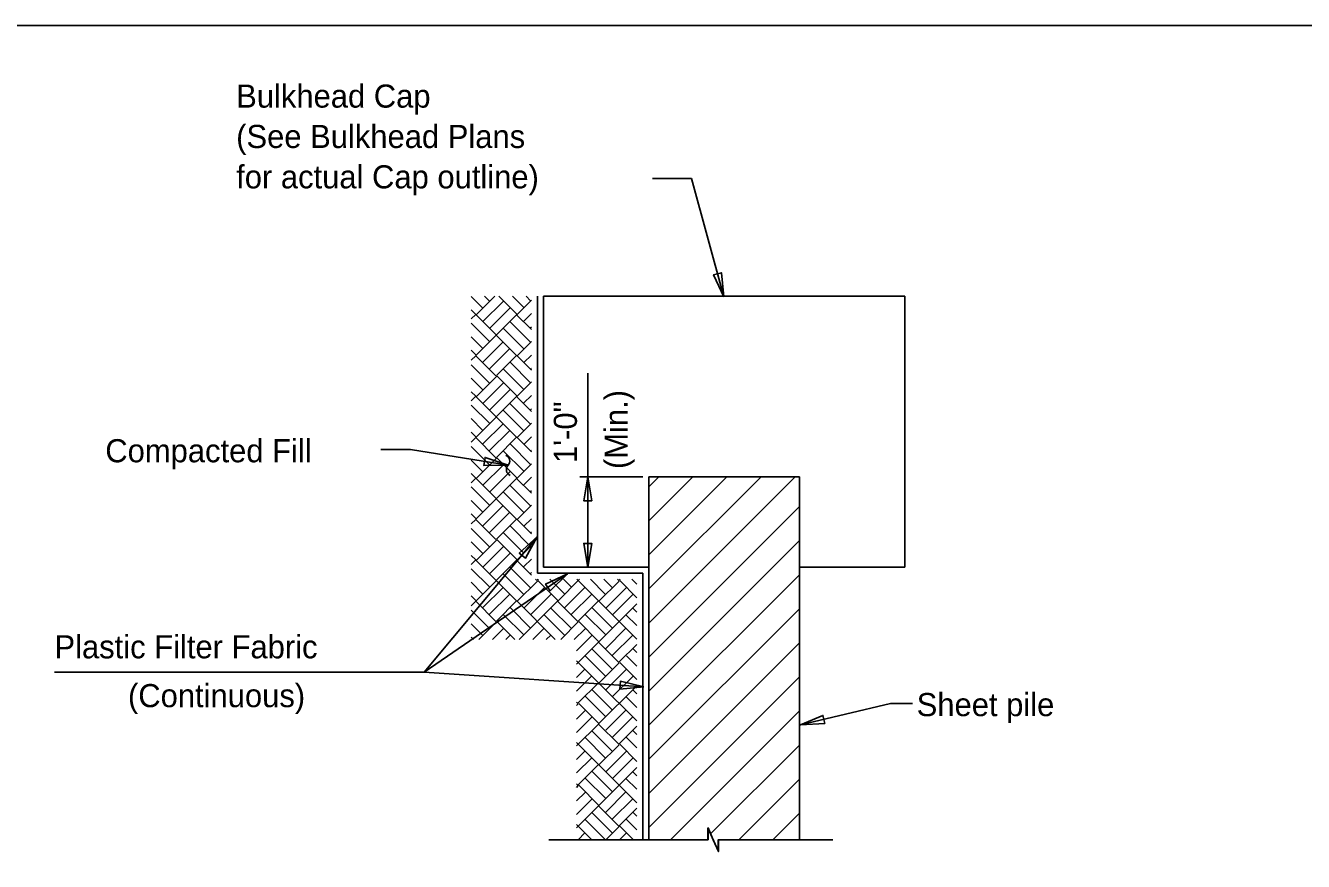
# Model space of a CAD drawing. Extents: x 111162.5 to 111216.6, y 110741.1 to 110776.1.
# Drawn here: x 111170.9 to 111179.25, y 110768.77 to 110774.24 of the extents above; entities that cross this region are included whole.
import ezdxf

# ---------------------------------------------------------------- set-up
doc = ezdxf.new("R2010")
doc.units = 0
for name, color, linetype in [('AdhocPoint_dp', 7, 'Continuous'), ('Border', 7, 'Continuous'), ('Patterning', 7, 'Continuous'), ('PlotBorder_dp', 7, 'Continuous'), ('SheetBorder_dp', 7, 'Continuous'), ('TextMisc', 7, 'Continuous'), ('Viewport', 7, 'Continuous')]:
    doc.layers.add(name, color=color, linetype=linetype)

msp = doc.modelspace()

# ---------------------------------------------------------------- linework, layer by layer
at = {"layer": 'AdhocPoint_dp'}
for p, q in [((111174.2855, 110770.6961), (111174.2855, 110772.468)), ((111174.2855, 110772.468), (111176.6479, 110772.468)), ((111176.6479, 110772.468), (111176.6479, 110770.6961)), ((111174.9745, 110770.6961), (111174.2855, 110770.6961)), ((111175.9589, 110770.6961), (111176.6479, 110770.6961))]:
    msp.add_line(p, q, dxfattribs=at)
at = {"layer": 'Border'}
for p, q in [((111174.2461, 110770.6567), (111174.2461, 110772.468)), ((111174.9351, 110770.6567), (111174.2461, 110770.6567)), ((111174.9351, 110768.914), (111174.9351, 110770.6567))]:
    msp.add_line(p, q, dxfattribs=at)
at = {"layer": 'Patterning'}
for p, q in [((111174.5752, 110770.6961), (111174.5752, 110771.9642)), ((111174.934, 110771.2867), (111174.5228, 110771.2867)), ((111174.443, 110770.6523), (111173.5051, 110770.0105)), ((111174.9422, 110769.9147), (111173.5051, 110770.0105)), ((111174.3208, 110768.914), (111175.2889, 110768.914)), ((111175.4996, 110768.914), (111176.1761, 110768.914))]:
    msp.add_line(p, q, dxfattribs=at)
for points in [[(111175.4639, 110772.4646), (111175.2528, 110773.2371), (111174.9989, 110773.2371)], [(111174.0543, 110771.3626), (111173.417, 110771.4664), (111173.2225, 110771.4664)], [(111174.2451, 110770.8947), (111173.5051, 110770.0105), (111171.0902, 110770.0105)], [(111175.9661, 110769.6648), (111176.5542, 110769.8045), (111176.698, 110769.8045)], [(111175.2889, 110768.914), (111175.3608, 110768.914), (111175.3608, 110768.9921), (111175.4277, 110768.8409), (111175.4277, 110768.914), (111175.4996, 110768.914)], [(111175.2892, 110768.914), (111175.3617, 110768.914), (111175.3617, 110768.9915), (111175.3954, 110768.914), (111175.4292, 110768.8365), (111175.4292, 110768.914), (111175.5017, 110768.914)]]:
    msp.add_lwpolyline(points, dxfattribs=at)
for points in [[(111175.4639, 110772.4646), (111175.4487, 110772.6223), (111175.3976, 110772.6085)], [(111174.0543, 110771.3626), (111173.9044, 110771.4138), (111173.8959, 110771.3616)], [(111174.5752, 110771.2867), (111174.5487, 110771.1305), (111174.6016, 110771.1305)], [(111174.2451, 110770.8947), (111174.1271, 110770.789), (111174.1685, 110770.756)], [(111174.5752, 110770.6961), (111174.6016, 110770.8523), (111174.5487, 110770.8523)], [(111174.443, 110770.6523), (111174.2993, 110770.5856), (111174.3293, 110770.542)], [(111174.9422, 110769.9147), (111174.788, 110769.9511), (111174.7846, 110769.8983)], [(111175.9661, 110769.6648), (111176.1242, 110769.6753), (111176.1119, 110769.7268)]]:
    msp.add_lwpolyline(points, close=True, dxfattribs=at)
for centre, start, end in [((111174.025, 110771.3908), 316.04656, 67.77378), ((111174.0836, 110771.3344), 136.04656, 247.77378)]:
    msp.add_arc(centre, 0.0406, start, end, dxfattribs=at)
at = {"layer": 'PlotBorder_dp'}
for p, q in [((111174.9745, 110768.914), (111174.9745, 110771.2867)), ((111174.9745, 110771.2867), (111175.9589, 110771.2867)), ((111175.9589, 110771.2867), (111175.9589, 110768.914))]:
    msp.add_line(p, q, dxfattribs=at)
at = {"layer": 'TextMisc'}
for p, q in [((111173.813, 110772.4675), (111173.887, 110772.3934)), ((111173.9671, 110772.468), (111173.8455, 110772.3464)), ((111174.0224, 110772.4348), (111173.8898, 110772.3021)), ((111173.9007, 110772.468), (111173.9311, 110772.4376)), ((111174.1132, 110772.3496), (111173.9948, 110772.468)), ((111174.1573, 110772.3937), (111174.0831, 110772.468)), ((111174.2067, 110772.443), (111174.1132, 110772.3496)), ((111174.2016, 110772.438), (111174.1717, 110772.468)), ((111173.8428, 110772.3492), (111173.813, 110772.379)), ((111173.8428, 110772.3492), (111173.813, 110772.3194)), ((111174.1103, 110772.0816), (111173.8455, 110772.3464)), ((111174.1105, 110772.3468), (111173.8456, 110772.082)), ((111174.0666, 110772.3906), (111173.9339, 110772.258)), ((111174.1105, 110772.3468), (111174.2067, 110772.2505)), ((111174.2067, 110772.3548), (111174.1573, 110772.3055)), ((111173.9341, 110772.1704), (111173.813, 110772.2915)), ((111174.0661, 110772.3025), (111174.1987, 110772.17)), ((111174.2067, 110772.2665), (111174.2015, 110772.2613)), ((111173.8898, 110772.1261), (111173.813, 110772.203)), ((111174.022, 110772.2584), (111174.1546, 110772.1259)), ((111173.8456, 110772.082), (111173.813, 110772.1147)), ((111174.0219, 110772.17), (111173.8898, 110772.0379)), ((111174.066, 110772.1259), (111173.9339, 110771.9938)), ((111174.2067, 110772.1724), (111174.1131, 110772.0788)), ((111173.8429, 110772.0792), (111173.813, 110772.0493)), ((111173.813, 110772.0206), (111173.9311, 110771.9024)), ((111173.8429, 110772.0792), (111173.9754, 110771.9467)), ((111174.1103, 110772.0816), (111173.9782, 110771.9495)), ((111174.2016, 110771.9029), (111174.0694, 110772.0351)), ((111174.2067, 110771.9852), (111174.1131, 110772.0788)), ((111174.2067, 110772.0839), (111174.1573, 110772.0345)), ((111173.813, 110771.9323), (111173.887, 110771.8583)), ((111173.9782, 110771.9439), (111173.8455, 110771.8112)), ((111174.1132, 110771.8144), (111173.9809, 110771.9467)), ((111174.1573, 110771.8586), (111174.0251, 110771.9908)), ((111174.2067, 110771.9956), (111174.2015, 110771.9904)), ((111173.8428, 110771.814), (111173.813, 110771.8438)), ((111174.0224, 110771.8996), (111173.8898, 110771.767)), ((111174.0666, 110771.8555), (111173.9339, 110771.7229)), ((111174.2067, 110771.9079), (111174.1132, 110771.8144)), ((111173.8428, 110771.814), (111173.813, 110771.7843)), ((111174.1103, 110771.5465), (111173.8455, 110771.8112)), ((111174.1105, 110771.8117), (111173.8456, 110771.5469)), ((111174.0661, 110771.7674), (111174.1987, 110771.6349)), ((111174.1105, 110771.8117), (111174.2067, 110771.7154)), ((111174.2067, 110771.8197), (111174.1573, 110771.7703)), ((111173.9341, 110771.6353), (111173.813, 110771.7564)), ((111174.022, 110771.7233), (111174.1546, 110771.5907)), ((111174.2067, 110771.7314), (111174.2015, 110771.7262)), ((111173.8898, 110771.591), (111173.813, 110771.6679)), ((111174.0219, 110771.6349), (111173.8898, 110771.5028)), ((111174.2067, 110771.6373), (111174.1131, 110771.5437)), ((111173.8456, 110771.5469), (111173.813, 110771.5796)), ((111173.8429, 110771.5441), (111173.813, 110771.5142)), ((111173.8429, 110771.5441), (111173.9754, 110771.4116)), ((111174.066, 110771.5907), (111173.9339, 110771.4586)), ((111174.1103, 110771.5465), (111173.9782, 110771.4144)), ((111174.2067, 110771.4501), (111174.1131, 110771.5437)), ((111174.2067, 110771.5488), (111174.1573, 110771.4994)), ((111173.813, 110771.4855), (111173.9311, 110771.3673)), ((111174.1573, 110771.3235), (111174.0251, 110771.4557)), ((111174.2016, 110771.3677), (111174.0694, 110771.5)), ((111174.2067, 110771.4605), (111174.2015, 110771.4553)), ((111173.813, 110771.3972), (111173.887, 110771.3232)), ((111173.9782, 110771.4088), (111173.8455, 110771.2761)), ((111174.0224, 110771.3645), (111173.8898, 110771.2319)), ((111174.1132, 110771.2793), (111173.9809, 110771.4116)), ((111174.2067, 110771.3728), (111174.1132, 110771.2793)), ((111173.8428, 110771.2789), (111173.813, 110771.3087)), ((111173.8428, 110771.2789), (111173.813, 110771.2491)), ((111174.1103, 110771.0114), (111173.8455, 110771.2761)), ((111174.1105, 110771.2766), (111173.8456, 110771.0118)), ((111174.0666, 110771.3204), (111173.9339, 110771.1877)), ((111174.1105, 110771.2766), (111174.2067, 110771.1803)), ((111174.2067, 110771.2846), (111174.1573, 110771.2352)), ((111174.9745, 110770.9994), (111175.2618, 110771.2867)), ((111174.9745, 110770.7767), (111175.4845, 110771.2867)), ((111174.9745, 110770.554), (111175.7072, 110771.2867)), ((111174.9745, 110770.3313), (111175.93, 110771.2867)), ((111174.9745, 110771.2221), (111175.0391, 110771.2867)), ((111173.9341, 110771.1002), (111173.813, 110771.2213)), ((111174.022, 110771.1882), (111174.1546, 110771.0556)), ((111174.0661, 110771.2323), (111174.1987, 110771.0997)), ((111174.2067, 110771.1963), (111174.2015, 110771.1911)), ((111173.8898, 110771.0559), (111173.813, 110771.1328)), ((111174.0219, 110771.0997), (111173.8898, 110770.9677)), ((111174.2067, 110771.1022), (111174.1131, 110771.0085)), ((111174.9745, 110770.1085), (111175.9589, 110771.0929)), ((111173.8456, 110771.0118), (111173.813, 110771.0445)), ((111173.8429, 110771.009), (111173.813, 110770.9791)), ((111173.8429, 110771.009), (111173.9754, 110770.8765)), ((111174.066, 110771.0556), (111173.9339, 110770.9235)), ((111174.1103, 110771.0114), (111173.9782, 110770.8792)), ((111174.2067, 110770.9149), (111174.1131, 110771.0085)), ((111174.2067, 110771.0136), (111174.1573, 110770.9643)), ((111173.813, 110770.9504), (111173.9311, 110770.8322)), ((111174.2016, 110770.8326), (111174.0694, 110770.9648)), ((111174.2067, 110770.9254), (111174.2015, 110770.9202)), ((111173.813, 110770.8621), (111173.887, 110770.7881)), ((111173.9782, 110770.8736), (111173.8455, 110770.741)), ((111174.1132, 110770.7442), (111173.9809, 110770.8765)), ((111174.1573, 110770.7883), (111174.0251, 110770.9206)), ((111174.9745, 110769.8857), (111175.9589, 110770.8701)), ((111173.8428, 110770.7438), (111173.813, 110770.7736)), ((111174.0224, 110770.8294), (111173.8898, 110770.6967)), ((111174.0666, 110770.7853), (111173.9339, 110770.6526)), ((111174.2067, 110770.8377), (111174.1132, 110770.7442)), ((111173.8428, 110770.7438), (111173.813, 110770.714)), ((111173.9341, 110770.5651), (111173.813, 110770.6861)), ((111174.1103, 110770.4762), (111173.8455, 110770.741)), ((111174.1105, 110770.7414), (111173.8456, 110770.4766)), ((111174.0661, 110770.6971), (111174.1987, 110770.5646)), ((111174.1105, 110770.7414), (111174.2067, 110770.6452)), ((111174.2067, 110770.7494), (111174.1573, 110770.7001)), ((111173.8898, 110770.5208), (111173.813, 110770.5976)), ((111174.022, 110770.653), (111174.1546, 110770.5205)), ((111174.2458, 110770.6061), (111174.1131, 110770.4734)), ((111174.2067, 110770.6611), (111174.2015, 110770.6559)), ((111174.2345, 110770.6173), (111174.243, 110770.6089)), ((111174.2514, 110770.6173), (111174.2458, 110770.6117)), ((111174.3808, 110770.4766), (111174.2485, 110770.6089)), ((111174.4249, 110770.5208), (111174.3283, 110770.6173)), ((111174.5215, 110770.6173), (111174.3808, 110770.4766)), ((111174.4692, 110770.5651), (111174.4169, 110770.6173)), ((111174.6454, 110770.4762), (111174.5043, 110770.6173)), ((111174.5929, 110770.6173), (111174.6897, 110770.5205)), ((111174.7809, 110770.6061), (111174.6482, 110770.4734)), ((111174.6811, 110770.6173), (111174.7338, 110770.5646)), ((111174.7696, 110770.6173), (111174.7781, 110770.6089)), ((111174.7866, 110770.6173), (111174.7809, 110770.6117)), ((111174.8957, 110770.4968), (111174.7836, 110770.6089)), ((111174.8957, 110770.5851), (111174.8635, 110770.6173)), ((111174.9745, 110769.663), (111175.9589, 110770.6473)), ((111173.8456, 110770.4766), (111173.813, 110770.5093)), ((111174.0219, 110770.5646), (111173.8898, 110770.4325)), ((111174.066, 110770.5205), (111173.9339, 110770.3884)), ((111174.29, 110770.5618), (111174.1573, 110770.4292)), ((111174.3342, 110770.5177), (111174.2015, 110770.3851)), ((111174.557, 110770.5646), (111174.4249, 110770.4325)), ((111174.6011, 110770.5205), (111174.4691, 110770.3884)), ((111174.8252, 110770.5618), (111174.6925, 110770.4292)), ((111174.8693, 110770.5177), (111174.7366, 110770.3851)), ((111173.8429, 110770.4739), (111173.813, 110770.444)), ((111173.8429, 110770.4739), (111173.9754, 110770.3413)), ((111174.1103, 110770.4762), (111173.9782, 110770.3441)), ((111174.2016, 110770.2975), (111174.0694, 110770.4297)), ((111174.3629, 110770.2236), (111174.1131, 110770.4734)), ((111174.378, 110770.4739), (111174.1277, 110770.2236)), ((111174.3338, 110770.4296), (111174.4662, 110770.2971)), ((111174.378, 110770.4739), (111174.5105, 110770.3413)), ((111174.6454, 110770.4762), (111174.5133, 110770.3441)), ((111174.7367, 110770.2975), (111174.6045, 110770.4297)), ((111174.8957, 110770.2259), (111174.6482, 110770.4734)), ((111174.8957, 110770.4565), (111174.6483, 110770.2091)), ((111174.8689, 110770.4296), (111174.8957, 110770.4027)), ((111174.9745, 110769.4403), (111175.9589, 110770.4247)), ((111173.813, 110770.4152), (111173.9311, 110770.2971)), ((111174.0987, 110770.2236), (111173.9809, 110770.3413)), ((111174.1573, 110770.2532), (111174.0251, 110770.3855)), ((111174.2896, 110770.3855), (111174.4221, 110770.2529)), ((111174.6483, 110770.2091), (111174.5161, 110770.3413)), ((111174.6925, 110770.2532), (111174.5602, 110770.3855)), ((111174.8247, 110770.3855), (111174.8957, 110770.3144)), ((111173.813, 110770.327), (111173.887, 110770.2529)), ((111173.9782, 110770.3385), (111173.8632, 110770.2236)), ((111174.0224, 110770.2943), (111173.9518, 110770.2236)), ((111174.2895, 110770.2971), (111174.216, 110770.2236)), ((111174.5133, 110770.3385), (111174.3983, 110770.2236)), ((111174.5576, 110770.2943), (111174.4869, 110770.2236)), ((111174.8246, 110770.2971), (111174.6925, 110770.1649)), ((111173.8278, 110770.2236), (111173.813, 110770.2384)), ((111174.0666, 110770.2502), (111174.04, 110770.2236)), ((111174.3336, 110770.2529), (111174.3043, 110770.2236)), ((111174.6017, 110770.2502), (111174.502, 110770.1504)), ((111174.6456, 110770.2063), (111174.502, 110770.0627)), ((111174.6456, 110770.2063), (111174.7781, 110770.0738)), ((111174.8687, 110770.2529), (111174.7366, 110770.1208)), ((111174.8957, 110770.1914), (111174.7809, 110770.0766)), ((111174.9745, 110769.2176), (111175.9589, 110770.2019)), ((111174.5572, 110770.1179), (111174.6897, 110769.9854)), ((111174.6013, 110770.162), (111174.7338, 110770.0295)), ((111174.8957, 110770.0499), (111174.8278, 110770.1179)), ((111174.8957, 110770.1385), (111174.872, 110770.1622)), ((111174.6454, 110769.9411), (111174.502, 110770.0845)), ((111174.557, 110770.0295), (111174.502, 110769.9745)), ((111174.7809, 110770.071), (111174.6482, 110769.9383)), ((111174.8252, 110770.0267), (111174.6925, 110769.8941)), ((111174.8957, 110769.9617), (111174.7836, 110770.0738)), ((111174.6011, 110769.9854), (111174.502, 110769.8862)), ((111174.6454, 110769.9411), (111174.5133, 110769.809)), ((111174.8957, 110769.6908), (111174.6482, 110769.9383)), ((111174.8693, 110769.9826), (111174.7366, 110769.8499)), ((111174.9745, 110768.9948), (111175.9589, 110769.9792)), ((111174.6925, 110769.7181), (111174.5602, 110769.8504)), ((111174.7367, 110769.7623), (111174.6045, 110769.8946)), ((111174.8957, 110769.9214), (111174.6483, 110769.674)), ((111174.8247, 110769.8504), (111174.8957, 110769.7793)), ((111174.8689, 110769.8945), (111174.8957, 110769.8676)), ((111174.502, 110769.8147), (111174.5105, 110769.8062)), ((111174.5133, 110769.8034), (111174.502, 110769.7921)), ((111174.5576, 110769.7592), (111174.502, 110769.7036)), ((111174.6483, 110769.674), (111174.5161, 110769.8062)), ((111174.8246, 110769.7619), (111174.6925, 110769.6298)), ((111175.1164, 110768.914), (111175.9589, 110769.7565)), ((111174.6017, 110769.715), (111174.502, 110769.6153)), ((111174.6456, 110769.6711), (111174.502, 110769.5276)), ((111174.6456, 110769.6711), (111174.7781, 110769.5386)), ((111174.8687, 110769.7178), (111174.7366, 110769.5857)), ((111174.6013, 110769.6269), (111174.7338, 110769.4944)), ((111174.8957, 110769.6563), (111174.7809, 110769.5414)), ((111174.8957, 110769.6033), (111174.872, 110769.627)), ((111174.6454, 110769.406), (111174.502, 110769.5494)), ((111174.5572, 110769.5828), (111174.6897, 110769.4503)), ((111174.7809, 110769.5358), (111174.6482, 110769.4032)), ((111174.8957, 110769.4266), (111174.7836, 110769.5386)), ((111174.8957, 110769.5148), (111174.8278, 110769.5828)), ((111175.3781, 110768.953), (111175.9589, 110769.5337)), ((111174.557, 110769.4944), (111174.502, 110769.4394)), ((111174.6011, 110769.4503), (111174.502, 110769.3511)), ((111174.8252, 110769.4916), (111174.6925, 110769.3589)), ((111174.8693, 110769.4474), (111174.7366, 110769.3148)), ((111174.6454, 110769.406), (111174.5133, 110769.2739)), ((111174.7367, 110769.2272), (111174.6045, 110769.3595)), ((111174.8957, 110769.1556), (111174.6482, 110769.4032)), ((111174.8957, 110769.3863), (111174.6483, 110769.1388)), ((111174.8689, 110769.3593), (111174.8957, 110769.3324)), ((111174.502, 110769.2796), (111174.5105, 110769.2711)), ((111174.5133, 110769.2683), (111174.502, 110769.257)), ((111174.6483, 110769.1388), (111174.5161, 110769.2711)), ((111174.6925, 110769.183), (111174.5602, 110769.3152)), ((111174.8247, 110769.3152), (111174.8957, 110769.2442)), ((111175.5619, 110768.914), (111175.9589, 110769.3109)), ((111174.5576, 110769.224), (111174.502, 110769.1684)), ((111174.6017, 110769.1799), (111174.502, 110769.0802)), ((111174.8246, 110769.2268), (111174.6925, 110769.0947)), ((111174.8687, 110769.1827), (111174.7366, 110769.0506)), ((111174.6456, 110769.136), (111174.502, 110768.9925)), ((111174.6013, 110769.0918), (111174.7338, 110768.9593)), ((111174.6456, 110769.136), (111174.7781, 110769.0035)), ((111174.8957, 110769.1212), (111174.7809, 110769.0063)), ((111174.8957, 110769.0682), (111174.872, 110769.0919)), ((111175.7846, 110768.914), (111175.9589, 110769.0882)), ((111174.6023, 110768.914), (111174.502, 110769.0143)), ((111174.5572, 110769.0477), (111174.6897, 110768.9151)), ((111174.8732, 110768.914), (111174.7836, 110769.0035)), ((111174.8957, 110768.9797), (111174.8278, 110769.0477)), ((111174.557, 110768.9593), (111174.5117, 110768.914)), ((111174.7809, 110769.0007), (111174.6941, 110768.914)), ((111174.8252, 110768.9565), (111174.7827, 110768.914)), ((111174.6011, 110768.9151), (111174.6, 110768.914))]:
    msp.add_line(p, q, dxfattribs=at)
at = {"layer": 'Viewport'}
msp.add_lwpolyline([(111162.5509, 110774.2382), (111193.3509, 110774.2382), (111193.3509, 110754.4382), (111162.5509, 110754.4382)], close=True, dxfattribs=at)

# ---------------------------------------------------------------- texts
at = {"layer": 'Patterning'}
for s, p in [('Bulkhead Cap', (111172.2776, 110773.7014)), ('(See Bulkhead Plans', (111172.2776, 110773.4374)), ('for actual Cap outline)', (111172.2776, 110773.1734)), ('Plastic Filter Fabric', (111171.0903, 110770.1004)), ('(Continuous)', (111171.5707, 110769.7812))]:
    msp.add_text(s, height=0.1512, dxfattribs=at).set_placement(p)
at = {"layer": 'SheetBorder_dp'}
for s, p in [('(Min.)', (111174.8357, 110771.3383)), ('1\'-0"', (111174.5044, 110771.3776))]:
    msp.add_text(s, height=0.1512, rotation=90, dxfattribs=at).set_placement(p)
for s, p in [('Compacted Fill', (111171.4224, 110771.3824)), ('Sheet pile', (111176.7245, 110769.7224))]:
    msp.add_text(s, height=0.1512, dxfattribs=at).set_placement(p)

doc.saveas('drawing.dxf')
